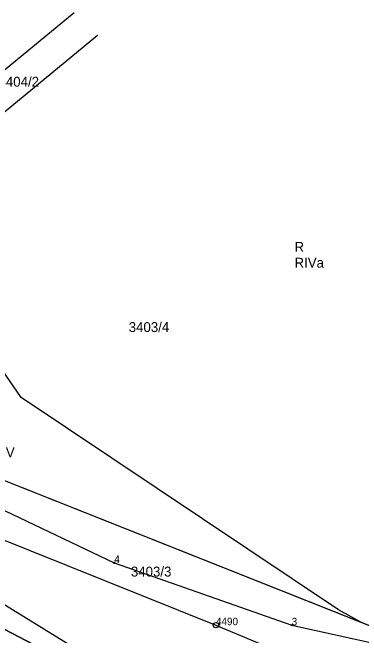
# Model space of a CAD drawing. Extents: x 7492083 to 7492670, y 5466693 to 5467065.
# Drawn here: x 7492339.8 to 7492392.7, y 5466813.8 to 5466908.2 of the extents above; entities that cross this region are included whole.
import ezdxf

# ---------------------------------------------------------------- set-up
doc = ezdxf.new("R2010")
doc.units = 0
for name, color, linetype in [('202-punkt graniczny', 7, 'Continuous'), ('202-punkt graniczny-Atr103', 7, 'Continuous'), ('203-punkt graniczny', 7, 'Continuous'), ('203-punkt graniczny-Atr103', 7, 'Continuous'), ('209-oznaczenie konturu klasyfikacyjnego', 7, 'Continuous'), ('210-oznaczenie konturu użytku gruntowego', 7, 'Continuous'), ('211-numer działki ewidencyjnej', 7, 'Continuous'), ('217-kontur klasyfikacyjny', 7, 'Continuous'), ('218-kontur użytku gruntowego', 7, 'Continuous'), ('219-działka ewidencyjna', 7, 'Continuous')]:
    doc.layers.add(name, color=color, linetype=linetype)

# ---------------------------------------------------------------- blocks, each defined once
blk = doc.blocks.new('203')
blk.add_circle((0, 0), 0.09)
blk = doc.blocks.new('202')
blk.add_circle((0, 0), 0.4)

msp = doc.modelspace()

# ---------------------------------------------------------------- linework, layer by layer
at = {"layer": '217-kontur klasyfikacyjny'}
for points in [[(7492341.15, 5466849.84), (7492331.33, 5466864.06)], [(7492389.2, 5466817.69), (7492341.15, 5466849.84)], [(7492325.52, 5466842.5), (7492392.56, 5466815.84)], [(7492392.56, 5466815.84), (7492389.2, 5466817.69)], [(7492392.56, 5466815.84), (7492408.22, 5466809.61)]]:
    msp.add_lwpolyline(points, dxfattribs=at)
at = {"layer": '218-kontur użytku gruntowego'}
for points in [[(7492341.15, 5466849.84), (7492331.33, 5466864.06)], [(7492389.2, 5466817.69), (7492341.15, 5466849.84)], [(7492325.52, 5466842.5), (7492392.56, 5466815.84)], [(7492392.56, 5466815.84), (7492389.2, 5466817.69)], [(7492351.02, 5466808.26), (7492335.01, 5466816.56)], [(7492392.56, 5466815.84), (7492408.22, 5466809.61)]]:
    msp.add_lwpolyline(points, dxfattribs=at)
at = {"layer": '219-działka ewidencyjna'}
for points in [[(7492335.07, 5466896.6), (7492349.181, 5466908.172)], [(7492325.85, 5466882.61), (7492352.682, 5466904.741)], [(7492325.52, 5466842.5), (7492408.22, 5466809.61)], [(7492300.27, 5466842.12), (7492349.95, 5466811.49)], [(7492330.94, 5466836.37), (7492355.23, 5466824.8)], [(7492331.01, 5466831.25), (7492370.62, 5466815.37)], [(7492355.23, 5466824.8), (7492382.09, 5466815.36)], [(7492335.01, 5466816.56), (7492351.02, 5466808.26)], [(7492370.62, 5466815.37), (7492396.75, 5466804.43)], [(7492382.09, 5466815.36), (7492408.22, 5466809.61)]]:
    msp.add_lwpolyline(points, dxfattribs=at)

# ---------------------------------------------------------------- block references
at = {"layer": '202-punkt graniczny'}
msp.add_blockref('202', (7492370.62, 5466815.37), dxfattribs=at)
at = {"layer": '203-punkt graniczny'}
for p in [(7492355.23, 5466824.8), (7492382.09, 5466815.36)]:
    msp.add_blockref('203', p, dxfattribs=at)

# ---------------------------------------------------------------- texts
at = {"layer": '202-punkt graniczny-Atr103'}
msp.add_text('4490', height=1.125, dxfattribs=at).set_placement((7492370.62, 5466815.37))
at = {"layer": '203-punkt graniczny-Atr103'}
for s, p in [('4', (7492355.23, 5466824.8)), ('3', (7492382.09, 5466815.36))]:
    msp.add_text(s, height=1.125, dxfattribs=at).set_placement(p)
at = {"layer": '209-oznaczenie konturu klasyfikacyjnego'}
for s, p in [('RIVa', (7492382.52, 5466869.52)), ('PsIV', (7492335.92, 5466840.8))]:
    msp.add_text(s, height=1.5, dxfattribs=at).set_placement(p)
at = {"layer": '210-oznaczenie konturu użytku gruntowego'}
msp.add_text('R', height=1.5, dxfattribs=at).set_placement((7492382.52, 5466871.92))
at = {"layer": '211-numer działki ewidencyjnej'}
for s, p in [('3404/2', (7492337.71, 5466896.93)), ('3403/4', (7492357.42, 5466859.77)), ('3403/3', (7492357.75, 5466822.74))]:
    msp.add_text(s, height=1.5, dxfattribs=at).set_placement(p)

doc.saveas('drawing.dxf')
